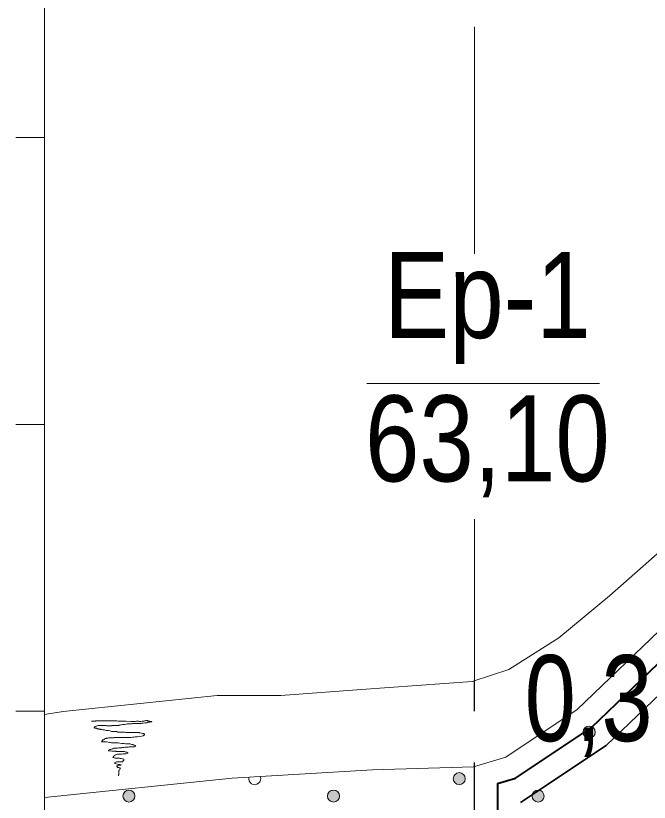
# Model space of a CAD drawing. Extents: x 640121 to 640955, y 6441885 to 6442246.
# Drawn here: x 640159.01 to 640181.1, y 6441965.23 to 6441992.66 of the extents above; entities that cross this region are included whole.
import ezdxf
from ezdxf.enums import TextEntityAlignment as Align

# ---------------------------------------------------------------- set-up
doc = ezdxf.new("R2010")
doc.units = 0
doc.header["$LTSCALE"] = 1.2
doc.linetypes.add('LONG_DASHED', pattern=[7.5, 6, -1.5])
doc.linetypes.add('MEDIUM_DASHED', pattern=[4.5, 3, -1.5])
for name, color, linetype, lineweight in [('30', 7, 'Continuous', 13), ('31', 7, 'Continuous', 13), ('32', 7, 'Continuous', 13), ('35', 7, 'Continuous', 35), ('40', 7, 'Continuous', 13), ('44', 7, 'Continuous', 13)]:
    doc.layers.add(name, color=color, linetype=linetype, lineweight=lineweight)

msp = doc.modelspace()

# ---------------------------------------------------------------- hatches: boundary and pattern name
at = {"layer": '44'}
for points in [[(640179.216, 6441967.675, 1), (640178.796, 6441967.675, 1)], [(640174.686, 6441966.05, 1), (640174.266, 6441966.05, 1)], [(640163.167, 6441965.444, 1), (640162.747, 6441965.444, 1)], [(640170.3, 6441965.444, 1), (640169.88, 6441965.444, 1)], [(640177.433, 6441965.444, 1), (640177.013, 6441965.444, 1)]]:
    msp.add_hatch(color=256, dxfattribs=at).paths.add_polyline_path(points)

# ---------------------------------------------------------------- linework, layer by layer
at = {"layer": '30'}
for p, q in [((640160.01, 6441898.41), (640160.01, 6442028.41)), ((640159.01, 6441988.41), (640160.01, 6441988.41)), ((640159.01, 6441978.41), (640160.01, 6441978.41)), ((640159.01, 6441968.41), (640160.01, 6441968.41))]:
    msp.add_line(p, q, dxfattribs=at)
at = {"layer": '31'}
for points in [[(640160.01, 6441965.39), (640166.56, 6441966.07), (640171.45, 6441966.36), (640174.97, 6441966.46), (640176.1, 6441966.8), (640178.59, 6441968.46), (640182.31, 6441972.03), (640184.02, 6441973.7), (640185.68, 6441975.56), (640188.37, 6441978.54), (640191.39, 6441982.77), (640193.92, 6441987.16), (640195.72, 6441990.26), (640196.56, 6441992.27), (640197.47, 6441994.09)], [(640160.01, 6441968.29), (640160.66, 6441968.39), (640166.03, 6441968.95), (640168.25, 6441968.95), (640171.07, 6441969.16), (640174.93, 6441969.44), (640176.2, 6441969.86), (640177.95, 6441970.96), (640179.71, 6441972.43), (640181.57, 6441974.07), (640183.43, 6441975.93), (640186.74, 6441979.44), (640192.4, 6441987.63), (640195.23, 6441993.58)]]:
    msp.add_lwpolyline(points, dxfattribs=at)
at = {"layer": '32'}
msp.add_line((640171.25, 6441979.83), (640179.36, 6441979.83), dxfattribs=at)
at = {"layer": '32', "linetype": 'LONG_DASHED', "lineweight": 25}
msp.add_line((640175.01, 6441914.41), (640175.01, 6441969.45), dxfattribs=at)
at = {"layer": '35', "lineweight": 13}
for p, q in [((640175.01, 6441984.36), (640175.01, 6441992.27)), ((640175.01, 6441969.47), (640175.01, 6441975.1))]:
    msp.add_line(p, q, dxfattribs=at)
at = {"layer": '35', "lineweight": 40}
msp.add_line((640175.81, 6441965.88), (640175.81, 6441915.21), dxfattribs=at)
msp.add_lwpolyline([(640175.81, 6441965.88), (640176.44, 6441966.07), (640179.09, 6441967.84), (640182.86, 6441971.46), (640184.6, 6441973.14), (640186.28, 6441975.02), (640188.99, 6441978.04), (640192.07, 6441982.34), (640194.62, 6441986.76), (640196.44, 6441989.9), (640197.29, 6441991.94), (640198.2, 6441993.76), (640199.11, 6441996.04), (640200.28, 6441998.44), (640201.91, 6442002.21), (640203.6, 6442005.87), (640204.29, 6442007.69)], dxfattribs=at)
at = {"layer": '35', "linetype": 'MEDIUM_DASHED'}
msp.add_lwpolyline([(640176.61, 6441965.22), (640179.6, 6441967.21), (640183.42, 6441970.88), (640185.17, 6441972.59), (640186.87, 6441974.49), (640189.62, 6441977.53), (640192.74, 6441981.9), (640195.31, 6441986.36), (640197.15, 6441989.55), (640198.02, 6441991.61), (640198.93, 6441993.44), (640199.85, 6441995.72), (640201.01, 6441998.1), (640202.64, 6442001.88), (640204.34, 6442005.56), (640205.04, 6442007.41)], dxfattribs=at)
at = {"layer": '40'}
for points in [[(640161.65, 6441968.06), (640161.68, 6441968.06), (640161.74, 6441968.06), (640161.79, 6441968.06), (640161.8, 6441968.07), (640161.86, 6441968.07), (640161.94, 6441968.07), (640162.1, 6441968.07), (640162.19, 6441968.07), (640162.21, 6441968.07), (640162.22, 6441968.07), (640162.26, 6441968.07), (640162.3, 6441968.07), (640162.36, 6441968.07), (640162.4, 6441968.07), (640162.43, 6441968.07), (640162.47, 6441968.07), (640162.51, 6441968.07), (640162.54, 6441968.07), (640162.58, 6441968.06), (640162.61, 6441968.06), (640162.64, 6441968.06), (640162.69, 6441968.06), (640162.86, 6441968.06), (640163.02, 6441968.05), (640163.06, 6441968.05), (640163.09, 6441968.05), (640163.11, 6441968.05), (640163.14, 6441968.05), (640163.17, 6441968.05), (640163.22, 6441968.06), (640163.24, 6441968.06), (640163.26, 6441968.06), (640163.27, 6441968.06), (640163.29, 6441968.06), (640163.33, 6441968.05), (640163.35, 6441968.05), (640163.37, 6441968.05), (640163.42, 6441968.06), (640163.45, 6441968.06), (640163.48, 6441968.06), (640163.5, 6441968.07), (640163.54, 6441968.07), (640163.56, 6441968.08), (640163.58, 6441968.08), (640163.6, 6441968.08), (640163.62, 6441968.07), (640163.64, 6441968.06), (640163.66, 6441968.06), (640163.68, 6441968.06)], [(640163.68, 6441968.06), (640163.71, 6441968.05), (640163.72, 6441968.05), (640163.75, 6441968.05), (640163.76, 6441968.04), (640163.75, 6441968.03), (640163.75, 6441968.04), (640163.74, 6441968.03), (640163.71, 6441968.03), (640163.68, 6441968.02), (640163.66, 6441968.02), (640163.64, 6441968.02), (640163.62, 6441968.02), (640163.6, 6441968.02), (640163.59, 6441968), (640163.56, 6441968), (640163.53, 6441968), (640163.51, 6441968), (640163.45, 6441967.99), (640163.42, 6441967.99), (640163.41, 6441967.99), (640163.38, 6441967.98), (640163.36, 6441967.98), (640163.34, 6441967.98), (640163.31, 6441967.97), (640163.29, 6441967.97), (640163.24, 6441967.97), (640163.21, 6441967.97), (640163.17, 6441967.97), (640163.13, 6441967.97), (640163.1, 6441967.97), (640163.08, 6441967.97), (640163.05, 6441967.96), (640163.02, 6441967.96), (640162.93, 6441967.96), (640162.91, 6441967.96), (640162.9, 6441967.96), (640162.86, 6441967.95), (640162.81, 6441967.94), (640162.77, 6441967.94), (640162.74, 6441967.94), (640162.7, 6441967.93), (640162.67, 6441967.93), (640162.64, 6441967.92), (640162.61, 6441967.92), (640162.6, 6441967.91), (640162.58, 6441967.91), (640162.55, 6441967.91), (640162.53, 6441967.91), (640162.51, 6441967.91), (640162.45, 6441967.9), (640162.42, 6441967.9)], [(640162.42, 6441967.9), (640162.4, 6441967.9), (640162.37, 6441967.9), (640162.36, 6441967.89), (640162.34, 6441967.89), (640162.32, 6441967.89), (640162.3, 6441967.89), (640162.27, 6441967.89), (640162.25, 6441967.89), (640162.21, 6441967.89), (640162.19, 6441967.89), (640162.16, 6441967.9), (640162.15, 6441967.9), (640162.13, 6441967.9), (640162.11, 6441967.9), (640162.09, 6441967.9), (640162.06, 6441967.9), (640162.03, 6441967.9), (640162.01, 6441967.9), (640161.99, 6441967.9), (640161.96, 6441967.9), (640161.94, 6441967.9), (640161.92, 6441967.9), (640161.9, 6441967.9), (640161.88, 6441967.9), (640161.85, 6441967.89), (640161.83, 6441967.88), (640161.81, 6441967.88), (640161.79, 6441967.87), (640161.78, 6441967.87), (640161.77, 6441967.86), (640161.76, 6441967.85), (640161.75, 6441967.83), (640161.76, 6441967.81), (640161.8, 6441967.81), (640161.83, 6441967.81), (640161.85, 6441967.79), (640161.88, 6441967.79), (640161.89, 6441967.79), (640161.91, 6441967.78), (640161.94, 6441967.78), (640161.96, 6441967.78), (640161.98, 6441967.77), (640162.01, 6441967.76), (640162.05, 6441967.75), (640162.09, 6441967.75), (640162.11, 6441967.75), (640162.13, 6441967.74), (640162.18, 6441967.73), (640162.23, 6441967.73)], [(640162.23, 6441967.73), (640162.3, 6441967.72), (640162.35, 6441967.7), (640162.38, 6441967.7), (640162.43, 6441967.69), (640162.48, 6441967.69), (640162.51, 6441967.69), (640162.54, 6441967.69), (640162.57, 6441967.67), (640162.61, 6441967.67), (640162.64, 6441967.67), (640162.68, 6441967.67), (640162.72, 6441967.67), (640162.76, 6441967.67), (640162.81, 6441967.67), (640162.85, 6441967.66), (640162.88, 6441967.66), (640162.9, 6441967.66), (640162.93, 6441967.66), (640162.97, 6441967.66), (640163.01, 6441967.66), (640163.06, 6441967.66), (640163.1, 6441967.66), (640163.13, 6441967.66), (640163.17, 6441967.66), (640163.19, 6441967.66), (640163.22, 6441967.66), (640163.25, 6441967.66), (640163.28, 6441967.66), (640163.31, 6441967.66), (640163.33, 6441967.65), (640163.4, 6441967.64), (640163.43, 6441967.63), (640163.46, 6441967.62), (640163.48, 6441967.61), (640163.5, 6441967.61), (640163.5, 6441967.59), (640163.5, 6441967.57), (640163.48, 6441967.57), (640163.47, 6441967.56), (640163.46, 6441967.55), (640163.44, 6441967.54), (640163.39, 6441967.53), (640163.32, 6441967.52), (640163.26, 6441967.51), (640163.22, 6441967.51), (640163.17, 6441967.51), (640163.13, 6441967.5), (640163.08, 6441967.5), (640163.02, 6441967.49), (640162.92, 6441967.49), (640162.84, 6441967.49)], [(640162.84, 6441967.49), (640162.79, 6441967.49), (640162.76, 6441967.49), (640162.72, 6441967.49), (640162.69, 6441967.49), (640162.66, 6441967.49), (640162.61, 6441967.49), (640162.57, 6441967.49), (640162.48, 6441967.49), (640162.44, 6441967.49), (640162.42, 6441967.48), (640162.37, 6441967.48), (640162.31, 6441967.47), (640162.25, 6441967.47), (640162.22, 6441967.46), (640162.19, 6441967.46), (640162.18, 6441967.46), (640162.16, 6441967.45), (640162.15, 6441967.45), (640162.13, 6441967.45), (640162.11, 6441967.44), (640162.1, 6441967.43), (640162.07, 6441967.41), (640162.05, 6441967.4), (640162.04, 6441967.39), (640162.03, 6441967.38), (640162.02, 6441967.37), (640162.01, 6441967.36), (640162, 6441967.34), (640162.01, 6441967.34), (640162.03, 6441967.34), (640162.06, 6441967.34), (640162.09, 6441967.34), (640162.14, 6441967.33), (640162.18, 6441967.33), (640162.23, 6441967.32), (640162.29, 6441967.31), (640162.32, 6441967.31), (640162.35, 6441967.3), (640162.38, 6441967.3), (640162.46, 6441967.3), (640162.53, 6441967.3), (640162.58, 6441967.3), (640162.64, 6441967.29), (640162.71, 6441967.28), (640162.78, 6441967.28), (640162.84, 6441967.27), (640162.88, 6441967.27), (640162.93, 6441967.27), (640162.97, 6441967.26)], [(640162.97, 6441967.26), (640163, 6441967.26), (640163.02, 6441967.25), (640163.06, 6441967.24), (640163.1, 6441967.24), (640163.12, 6441967.22), (640163.15, 6441967.22), (640163.18, 6441967.21), (640163.19, 6441967.21), (640163.2, 6441967.18), (640163.18, 6441967.18), (640163.17, 6441967.17), (640163.15, 6441967.16), (640163.09, 6441967.16), (640163.06, 6441967.16), (640163.05, 6441967.16), (640163.01, 6441967.16), (640162.97, 6441967.16), (640162.93, 6441967.15), (640162.9, 6441967.15), (640162.88, 6441967.15), (640162.81, 6441967.15), (640162.78, 6441967.14), (640162.76, 6441967.14), (640162.73, 6441967.14), (640162.71, 6441967.13), (640162.68, 6441967.13), (640162.64, 6441967.13), (640162.6, 6441967.13), (640162.56, 6441967.12), (640162.53, 6441967.12), (640162.51, 6441967.12), (640162.49, 6441967.12), (640162.47, 6441967.11), (640162.44, 6441967.11), (640162.43, 6441967.1), (640162.4, 6441967.09), (640162.39, 6441967.09), (640162.37, 6441967.09), (640162.35, 6441967.08), (640162.32, 6441967.07), (640162.29, 6441967.07), (640162.27, 6441967.06), (640162.25, 6441967.04), (640162.25, 6441967.02), (640162.27, 6441967.02), (640162.31, 6441967.02), (640162.36, 6441967.01), (640162.4, 6441967.01), (640162.42, 6441967.01), (640162.47, 6441967.01), (640162.5, 6441967.01)], [(640162.5, 6441967.01), (640162.51, 6441967), (640162.53, 6441967), (640162.56, 6441967), (640162.6, 6441967), (640162.61, 6441967), (640162.67, 6441967), (640162.71, 6441967), (640162.73, 6441967), (640162.75, 6441967), (640162.77, 6441967), (640162.8, 6441967), (640162.83, 6441966.99), (640162.85, 6441966.98), (640162.88, 6441966.97), (640162.9, 6441966.97), (640162.92, 6441966.96), (640162.92, 6441966.94), (640162.86, 6441966.92), (640162.78, 6441966.92), (640162.75, 6441966.92), (640162.7, 6441966.91), (640162.67, 6441966.91), (640162.63, 6441966.91), (640162.6, 6441966.91), (640162.56, 6441966.91), (640162.52, 6441966.89), (640162.48, 6441966.88), (640162.47, 6441966.86), (640162.45, 6441966.85), (640162.43, 6441966.84), (640162.42, 6441966.83), (640162.42, 6441966.81), (640162.4, 6441966.79), (640162.42, 6441966.79), (640162.44, 6441966.78), (640162.48, 6441966.77), (640162.54, 6441966.77), (640162.6, 6441966.76), (640162.63, 6441966.76), (640162.65, 6441966.75), (640162.69, 6441966.75), (640162.73, 6441966.74), (640162.78, 6441966.73), (640162.78, 6441966.7), (640162.77, 6441966.68), (640162.76, 6441966.67), (640162.73, 6441966.64), (640162.71, 6441966.64), (640162.68, 6441966.64), (640162.64, 6441966.64), (640162.6, 6441966.64), (640162.56, 6441966.64), (640162.52, 6441966.64), (640162.48, 6441966.62), (640162.47, 6441966.61), (640162.46, 6441966.59), (640162.47, 6441966.58), (640162.49, 6441966.58), (640162.55, 6441966.56), (640162.59, 6441966.55), (640162.61, 6441966.55), (640162.64, 6441966.54), (640162.67, 6441966.53), (640162.69, 6441966.52), (640162.68, 6441966.52), (640162.65, 6441966.52), (640162.61, 6441966.51), (640162.57, 6441966.5), (640162.55, 6441966.5), (640162.53, 6441966.5), (640162.53, 6441966.47), (640162.54, 6441966.46), (640162.55, 6441966.46), (640162.57, 6441966.44), (640162.6, 6441966.44), (640162.63, 6441966.43), (640162.65, 6441966.43), (640162.66, 6441966.4), (640162.64, 6441966.39), (640162.64, 6441966.37), (640162.63, 6441966.35), (640162.61, 6441966.34), (640162.61, 6441966.32), (640162.61, 6441966.29), (640162.61, 6441966.28), (640162.61, 6441966.26), (640162.61, 6441966.23), (640162.6, 6441966.22), (640162.6, 6441966.2), (640162.59, 6441966.18), (640162.59, 6441966.16), (640162.59, 6441966.15), (640162.59, 6441966.17)]]:
    msp.add_lwpolyline(points, dxfattribs=at)
at = {"layer": '44'}
for centre in [(640179.006, 6441967.675), (640174.476, 6441966.05), (640162.957, 6441965.444), (640170.09, 6441965.444), (640177.223, 6441965.444)]:
    msp.add_circle(centre, 0.21, dxfattribs=at)
msp.add_arc((640167.343, 6441966.05), 0.21, 165.1128, 21.7544, dxfattribs=at)

# ---------------------------------------------------------------- texts
at = {"layer": '32'}
for s, width, p in [('Ep-1', 0.85, (640175.455, 6441981.42)), ('63,10', 0.85, (640175.455, 6441976.42)), ('0,3', 0.8, (640178.985, 6441967.36))]:
    msp.add_text(s, height=3, dxfattribs=dict(at, width=width)).set_placement(p, align=Align.CENTER)

doc.saveas('drawing.dxf')
